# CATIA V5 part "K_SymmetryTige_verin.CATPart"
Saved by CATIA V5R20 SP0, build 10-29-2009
Part number: Symmetry of Tige_verin
Bounding box of the stored display mesh (mm): x -10 to 10, y -13.514 to 6.546, z -5.258 to 162.975
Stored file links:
  G:\Khaled_CFAO_2011\SIL\SIL_GR2\zthiebault\Khaled\CAD_ThinkMOTION\K_SymmetryTige_verin.CATPart
  G:\Khaled_CFAO_2011\SIL\SIL_GR2\zthiebault\Khaled\CAD_ThinkMOTION\K_Tige_verin.CATPart
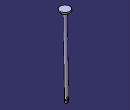
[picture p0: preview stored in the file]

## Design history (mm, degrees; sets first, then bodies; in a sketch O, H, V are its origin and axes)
Body1 (main body)
  Body2 "Corps du corps principal d'origine"
    Solid1: linked copy from another document
  Assemble1: tool Body2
